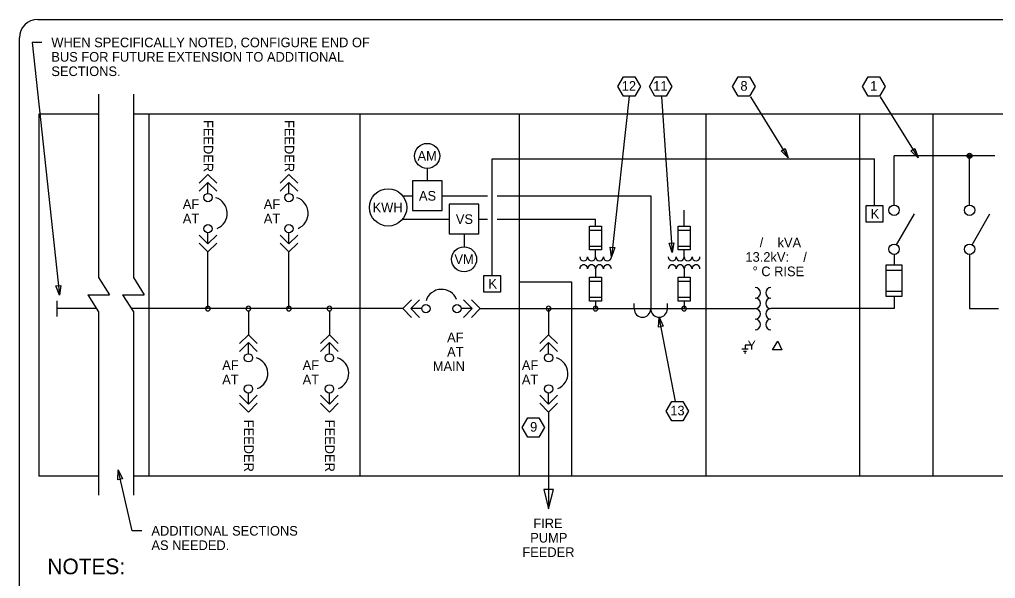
# Model space of a CAD drawing. Extents: x 10270 to 10376, y 10097 to 10174.
# Drawn here: x 10270.4 to 10338.1, y 10135.3 to 10174.1 of the extents above; entities that cross this region are included whole.
import ezdxf

# ---------------------------------------------------------------- set-up
doc = ezdxf.new("R2010")
doc.units = 0
for name, color, linetype in [('G-ANNO-TEXT', 7, 'Continuous'), ('G-ANNO-TTLB', 7, 'Continuous'), ('G-DETL-LINE', 7, 'Continuous'), ('G-DETL-OTLN', 7, 'Continuous'), ('G-DETL-PATT', 7, 'Continuous')]:
    doc.layers.add(name, color=color, linetype=linetype)

msp = doc.modelspace()

# ---------------------------------------------------------------- linework, layer by layer
at = {"layer": 'G-ANNO-TEXT'}
for p, q in [((10271.92, 10172.538), (10271.253, 10172.538)), ((10271.253, 10172.538), (10273.142, 10154.997)), ((10275.86, 10168.936), (10275.86, 10156.215)), ((10278.273, 10168.936), (10278.273, 10156.215)), ((10312.673, 10168.798), (10311.437, 10157.653)), ((10314.903, 10168.781), (10315.653, 10157.955)), ((10321.077, 10168.761), (10323.706, 10164.527)), ((10330.08, 10168.761), (10332.709, 10164.527)), ((10275.86, 10156.215), (10276.614, 10155.022)), ((10278.273, 10156.215), (10279.027, 10155.022)), ((10275.105, 10155.022), (10275.86, 10153.829)), ((10275.105, 10155.022), (10276.614, 10155.022)), ((10277.518, 10155.022), (10278.273, 10153.829)), ((10277.518, 10155.022), (10279.027, 10155.022)), ((10275.86, 10153.829), (10275.86, 10141.108)), ((10278.273, 10153.829), (10278.273, 10141.108)), ((10315.892, 10147.627), (10314.744, 10153.465)), ((10320.935, 10151.25), (10320.484, 10151.25)), ((10321.218, 10151.515), (10320.709, 10151.516)), ((10320.709, 10151.515), (10320.709, 10151.25)), ((10322.623, 10151.212), (10322.977, 10151.815)), ((10322.977, 10151.815), (10323.26, 10151.212)), ((10320.819, 10151.097), (10320.612, 10151.097)), ((10320.767, 10150.973), (10320.664, 10150.973)), ((10323.26, 10151.212), (10322.623, 10151.212)), ((10278.194, 10138.643), (10277.214, 10142.865)), ((10278.861, 10138.643), (10278.194, 10138.643))]:
    msp.add_line(p, q, dxfattribs=at)
for points in [[(10313.457, 10169.477), (10313.065, 10168.798), (10312.28, 10168.798), (10311.888, 10169.477), (10312.28, 10170.156), (10313.065, 10170.156)], [(10315.639, 10169.477), (10315.247, 10168.798), (10314.463, 10168.798), (10314.071, 10169.477), (10314.463, 10170.156), (10315.247, 10170.156)], [(10321.417, 10169.477), (10321.025, 10168.798), (10320.24, 10168.798), (10319.848, 10169.477), (10320.24, 10170.156), (10321.025, 10170.156)], [(10330.42, 10169.477), (10330.028, 10168.798), (10329.243, 10168.798), (10328.851, 10169.477), (10329.243, 10170.156), (10330.028, 10170.156)], [(10323.496, 10165.182), (10323.706, 10164.527), (10323.213, 10165.006)], [(10332.499, 10165.182), (10332.709, 10164.527), (10332.216, 10165.006)], [(10311.676, 10158.297), (10311.437, 10157.653), (10311.345, 10158.334)], [(10315.773, 10158.631), (10315.653, 10157.955), (10315.44, 10158.608)], [(10273.236, 10155.678), (10273.142, 10154.997), (10272.904, 10155.642)], [(10314.709, 10152.779), (10314.744, 10153.465), (10315.036, 10152.844)], [(10316.796, 10146.944), (10316.404, 10146.265), (10315.62, 10146.265), (10315.228, 10146.944), (10315.62, 10147.623), (10316.404, 10147.623)], [(10306.807, 10145.811), (10306.415, 10145.131), (10305.631, 10145.131), (10305.239, 10145.811), (10305.631, 10146.49), (10306.415, 10146.49)], [(10277.202, 10142.178), (10277.214, 10142.865), (10277.527, 10142.254)]]:
    msp.add_lwpolyline(points, close=True, dxfattribs=at)
at = {"layer": 'G-ANNO-TTLB'}
msp.add_line((10270.377, 10111.037), (10270.377, 10172.868), dxfattribs=at)
msp.add_lwpolyline([(10271.638, 10174.128), (10374.658, 10174.128)], dxfattribs=at)
msp.add_arc((10271.638, 10172.868), 1.261, 90, 180, dxfattribs=at)
at = {"layer": 'G-DETL-LINE'}
for p, q in [((10331.046, 10161.967), (10331.046, 10164.67)), ((10336.287, 10161.967), (10336.287, 10164.67)), ((10283.451, 10163.375), (10282.841, 10162.765)), ((10283.451, 10162.821), (10282.841, 10162.21)), ((10283.451, 10163.375), (10284.061, 10162.765)), ((10283.451, 10162.821), (10284.061, 10162.21)), ((10283.451, 10162.057), (10283.451, 10162.821)), ((10289.068, 10163.375), (10288.458, 10162.765)), ((10289.068, 10162.821), (10288.458, 10162.21)), ((10289.068, 10163.375), (10289.678, 10162.765)), ((10289.068, 10162.821), (10289.678, 10162.21)), ((10289.068, 10162.057), (10289.068, 10162.821)), ((10331.046, 10161.247), (10331.046, 10161.967)), ((10336.287, 10161.247), (10336.287, 10161.967)), ((10331.227, 10158.495), (10332.461, 10160.633)), ((10336.468, 10158.495), (10337.702, 10160.633)), ((10283.451, 10158.561), (10282.841, 10159.171)), ((10283.451, 10158.561), (10283.451, 10159.324)), ((10283.451, 10158.561), (10284.061, 10159.171)), ((10289.068, 10158.561), (10288.458, 10159.171)), ((10289.068, 10158.561), (10289.068, 10159.324)), ((10289.068, 10158.561), (10289.678, 10159.171)), ((10283.451, 10158.006), (10282.841, 10158.616)), ((10283.451, 10158.006), (10284.061, 10158.616)), ((10289.068, 10158.006), (10288.458, 10158.616)), ((10289.068, 10158.006), (10289.678, 10158.616)), ((10283.451, 10154.061), (10283.451, 10158.006)), ((10289.068, 10154.061), (10289.068, 10158.006)), ((10331.046, 10157.822), (10331.046, 10157.101)), ((10336.287, 10157.822), (10336.287, 10157.101)), ((10330.497, 10157.101), (10331.595, 10157.101)), ((10330.497, 10154.904), (10330.497, 10157.101)), ((10330.497, 10156.735), (10331.595, 10156.735)), ((10331.595, 10157.101), (10331.595, 10154.904)), ((10336.287, 10157.101), (10336.287, 10154.061)), ((10296.963, 10154.061), (10297.573, 10154.671)), ((10297.517, 10154.061), (10298.128, 10154.671)), ((10301.777, 10154.061), (10301.167, 10154.671)), ((10302.332, 10154.061), (10301.722, 10154.671)), ((10330.497, 10155.27), (10331.595, 10155.27)), ((10331.595, 10154.904), (10330.497, 10154.904)), ((10331.046, 10154.904), (10331.046, 10154.061)), ((10272.965, 10154.608), (10272.965, 10153.514)), ((10275.692, 10154.061), (10272.965, 10154.061)), ((10296.963, 10154.061), (10278.094, 10154.061)), ((10296.963, 10154.061), (10297.573, 10153.451)), ((10297.517, 10154.061), (10298.128, 10153.451)), ((10298.281, 10154.061), (10297.517, 10154.061)), ((10301.777, 10154.061), (10301.014, 10154.061)), ((10301.777, 10154.061), (10301.167, 10153.451)), ((10302.332, 10154.061), (10301.722, 10153.451)), ((10302.332, 10154.061), (10321.411, 10154.061)), ((10307.085, 10154.068), (10307.085, 10152.254)), ((10331.046, 10154.061), (10322.51, 10154.061)), ((10336.287, 10154.061), (10338.296, 10154.061)), ((10286.259, 10153.898), (10286.259, 10152.254)), ((10291.877, 10153.898), (10291.877, 10152.254)), ((10286.259, 10152.254), (10285.649, 10151.644)), ((10286.259, 10152.254), (10286.869, 10151.644)), ((10291.877, 10152.254), (10291.267, 10151.644)), ((10291.877, 10152.254), (10292.487, 10151.644)), ((10307.085, 10152.254), (10306.475, 10151.644)), ((10307.085, 10152.254), (10307.695, 10151.644)), ((10286.259, 10151.7), (10285.649, 10151.089)), ((10286.259, 10151.7), (10286.869, 10151.089)), ((10286.259, 10150.936), (10286.259, 10151.7)), ((10291.877, 10151.7), (10291.267, 10151.089)), ((10291.877, 10151.7), (10292.487, 10151.089)), ((10291.877, 10150.936), (10291.877, 10151.7)), ((10307.085, 10151.7), (10306.475, 10151.089)), ((10307.085, 10151.7), (10307.695, 10151.089)), ((10307.085, 10150.936), (10307.085, 10151.7)), ((10286.259, 10147.44), (10285.649, 10148.05)), ((10286.259, 10147.44), (10286.259, 10148.203)), ((10286.259, 10147.44), (10286.869, 10148.05)), ((10291.877, 10147.44), (10291.267, 10148.05)), ((10291.877, 10147.44), (10291.877, 10148.203)), ((10291.877, 10147.44), (10292.487, 10148.05)), ((10307.085, 10147.44), (10306.475, 10148.05)), ((10307.085, 10147.44), (10307.085, 10148.203)), ((10307.085, 10147.44), (10307.695, 10148.05)), ((10286.259, 10146.885), (10285.649, 10147.495)), ((10286.259, 10146.885), (10286.869, 10147.495)), ((10291.877, 10146.885), (10291.267, 10147.495)), ((10291.877, 10146.885), (10292.487, 10147.495)), ((10307.085, 10146.885), (10306.475, 10147.495)), ((10307.085, 10146.885), (10307.695, 10147.495)), ((10307.085, 10146.885), (10307.085, 10140.17))]:
    msp.add_line(p, q, dxfattribs=at)
msp.add_lwpolyline([(10338.046, 10164.67), (10331.046, 10164.67)], dxfattribs=at)
msp.add_lwpolyline([(10306.751, 10141.503), (10307.085, 10140.17), (10307.418, 10141.503)], close=True, dxfattribs=at)
for centre, radius in [((10336.287, 10164.67), 0.174), ((10336.287, 10164.67), 0.0977), ((10336.287, 10164.67), 0.0326), ((10283.451, 10161.769), 0.287), ((10289.068, 10161.769), 0.287), ((10331.046, 10160.886), 0.36), ((10336.287, 10160.886), 0.36), ((10283.451, 10159.611), 0.287), ((10289.068, 10159.611), 0.287), ((10331.046, 10158.182), 0.36), ((10336.287, 10158.182), 0.36), ((10298.569, 10154.061), 0.287), ((10300.727, 10154.061), 0.287), ((10286.259, 10150.648), 0.287), ((10291.877, 10150.648), 0.287), ((10307.085, 10150.648), 0.287), ((10286.259, 10148.49), 0.287), ((10291.877, 10148.49), 0.287), ((10307.085, 10148.49), 0.287)]:
    msp.add_circle(centre, radius, dxfattribs=at)
for centre, radius, start, end in [((10283.661, 10160.683), 1.13, 291.91165, 72.57617), ((10289.278, 10160.683), 1.13, 291.91165, 72.57617), ((10299.655, 10154.271), 1.13, 21.91165, 162.57617), ((10321.411, 10155.16), 0.366, 270.00003, 90.00003), ((10322.51, 10155.16), 0.366, 90.00003, 270.00003), ((10321.411, 10154.427), 0.366, 270.00003, 90.00003), ((10322.51, 10154.427), 0.366, 90.00003, 270.00003), ((10283.45, 10154.061), 0.163, 360, 180), ((10283.45, 10154.061), 0.163, 180, 0), ((10286.259, 10154.061), 0.163, 360, 180), ((10286.259, 10154.061), 0.163, 180, 0), ((10289.068, 10154.061), 0.163, 360, 180), ((10289.068, 10154.061), 0.163, 360, 180), ((10289.068, 10154.061), 0.163, 180, 0), ((10289.068, 10154.061), 0.163, 180, 0), ((10291.877, 10154.061), 0.163, 360, 180), ((10291.877, 10154.061), 0.163, 180, 0), ((10307.078, 10154.061), 0.163, 360, 180), ((10307.078, 10154.061), 0.163, 180, 0), ((10321.411, 10153.695), 0.366, 270.00003, 90.00003), ((10322.51, 10153.695), 0.366, 90.00003, 270.00003), ((10321.411, 10152.962), 0.366, 270.00003, 90.00003), ((10322.51, 10152.962), 0.366, 90.00003, 270.00003), ((10286.47, 10149.562), 1.13, 291.91165, 72.57617), ((10292.087, 10149.562), 1.13, 291.91165, 72.57617), ((10307.295, 10149.562), 1.13, 291.91165, 72.57617)]:
    msp.add_arc(centre, radius, start, end, dxfattribs=at)
at = {"layer": 'G-DETL-OTLN'}
for p, q in [((10275.86, 10167.562), (10271.724, 10167.562)), ((10271.724, 10167.562), (10271.724, 10142.435)), ((10344.565, 10167.562), (10278.273, 10167.562)), ((10279.349, 10167.562), (10279.349, 10142.435)), ((10293.975, 10167.562), (10293.975, 10142.435)), ((10305.045, 10167.562), (10305.045, 10142.435)), ((10317.991, 10167.562), (10317.991, 10142.435)), ((10328.655, 10167.562), (10328.655, 10142.435)), ((10333.749, 10167.562), (10333.749, 10142.435)), ((10275.86, 10142.435), (10271.724, 10142.435)), ((10344.565, 10142.435), (10278.273, 10142.435))]:
    msp.add_line(p, q, dxfattribs=at)
msp.add_lwpolyline([(10305.071, 10155.917), (10308.676, 10155.917), (10308.676, 10142.435)], dxfattribs=at)
at = {"layer": 'G-DETL-PATT'}
for p, q in [((10329.693, 10161.227), (10329.693, 10164.455)), ((10298.659, 10163.793), (10298.659, 10162.921)), ((10296.957, 10161.894), (10297.632, 10161.894)), ((10299.687, 10161.894), (10302.844, 10161.894)), ((10303.511, 10161.894), (10314.168, 10161.894)), ((10314.168, 10161.894), (10314.168, 10154.061)), ((10316.485, 10159.782), (10316.485, 10160.89)), ((10296.957, 10160.275), (10300.191, 10160.275)), ((10302.246, 10160.275), (10302.844, 10160.275)), ((10303.511, 10160.275), (10310.338, 10160.275)), ((10310.338, 10159.782), (10310.338, 10160.275)), ((10309.926, 10159.782), (10310.75, 10159.782)), ((10309.926, 10158.134), (10309.926, 10159.782)), ((10309.926, 10159.507), (10310.75, 10159.507)), ((10310.75, 10159.782), (10310.75, 10158.134)), ((10316.073, 10159.782), (10316.897, 10159.782)), ((10316.073, 10158.134), (10316.073, 10159.782)), ((10316.073, 10159.507), (10316.897, 10159.507)), ((10316.897, 10159.782), (10316.897, 10158.134)), ((10301.219, 10159.247), (10301.219, 10158.356)), ((10309.926, 10158.408), (10310.75, 10158.408)), ((10310.75, 10158.134), (10309.926, 10158.134)), ((10310.338, 10157.653), (10310.338, 10158.134)), ((10316.073, 10158.408), (10316.897, 10158.408)), ((10316.897, 10158.134), (10316.073, 10158.134)), ((10316.485, 10157.653), (10316.485, 10158.134)), ((10310.338, 10156.829), (10310.338, 10156.239)), ((10316.485, 10156.829), (10316.485, 10156.239)), ((10309.926, 10156.239), (10310.75, 10156.239)), ((10309.926, 10154.591), (10309.926, 10156.239)), ((10310.75, 10156.239), (10310.75, 10154.591)), ((10316.073, 10156.239), (10316.897, 10156.239)), ((10316.073, 10154.591), (10316.073, 10156.239)), ((10316.897, 10156.239), (10316.897, 10154.591)), ((10309.926, 10155.965), (10310.75, 10155.965)), ((10316.073, 10155.965), (10316.897, 10155.965)), ((10309.926, 10154.866), (10310.75, 10154.866)), ((10316.073, 10154.866), (10316.897, 10154.866)), ((10310.75, 10154.591), (10309.926, 10154.591)), ((10310.338, 10154.591), (10310.338, 10154.061)), ((10313.017, 10154.04), (10313.017, 10154.412)), ((10315.319, 10154.04), (10315.319, 10154.412)), ((10316.897, 10154.591), (10316.073, 10154.591)), ((10316.485, 10154.591), (10316.485, 10154.061))]:
    msp.add_line(p, q, dxfattribs=at)
msp.add_lwpolyline([(10303.177, 10156.37), (10303.177, 10164.455), (10329.694, 10164.455)], dxfattribs=at)
for points in [[(10299.687, 10162.921), (10297.632, 10162.921), (10297.632, 10160.866), (10299.687, 10160.866)], [(10302.246, 10161.302), (10300.191, 10161.302), (10300.191, 10159.247), (10302.246, 10159.247)], [(10329.114, 10160.07), (10329.114, 10161.227), (10330.272, 10161.227), (10330.272, 10160.07)], [(10302.598, 10155.212), (10302.598, 10156.37), (10303.756, 10156.37), (10303.756, 10155.212)]]:
    msp.add_lwpolyline(points, close=True, dxfattribs=at)
for centre, radius in [((10298.659, 10164.663), 0.87), ((10295.947, 10161.084), 1.294), ((10301.219, 10157.486), 0.87)]:
    msp.add_circle(centre, radius, dxfattribs=at)
for centre, radius, start, end in [((10309.514, 10157.653), 0.275, 180.00003, 0.00003), ((10310.063, 10157.653), 0.275, 180.00003, 0.00003), ((10310.613, 10157.653), 0.275, 180.00003, 0.00003), ((10311.163, 10157.653), 0.275, 180.00003, 0.00003), ((10315.661, 10157.653), 0.275, 180.00003, 0.00003), ((10316.21, 10157.653), 0.275, 180.00003, 0.00003), ((10316.76, 10157.653), 0.275, 180.00003, 0.00003), ((10317.309, 10157.653), 0.275, 180.00003, 0.00003), ((10309.514, 10156.829), 0.275, 0.00003, 180.00003), ((10310.063, 10156.829), 0.275, 0.00003, 180.00003), ((10310.613, 10156.829), 0.275, 0.00003, 180.00003), ((10311.163, 10156.829), 0.275, 0.00003, 180.00003), ((10315.661, 10156.829), 0.275, 0.00003, 180.00003), ((10316.21, 10156.829), 0.275, 0.00003, 180.00003), ((10316.76, 10156.829), 0.275, 0.00003, 180.00003), ((10317.309, 10156.829), 0.275, 0.00003, 180.00003), ((10310.338, 10154.061), 0.163, 360, 180), ((10310.338, 10154.061), 0.163, 180, 0), ((10313.593, 10154.041), 0.575, 180, 0), ((10314.744, 10154.041), 0.575, 180, 0), ((10316.485, 10154.061), 0.163, 360, 180), ((10316.485, 10154.061), 0.163, 180, 0)]:
    msp.add_arc(centre, radius, start, end, dxfattribs=at)

# ---------------------------------------------------------------- texts
at = {"layer": 'G-ANNO-TEXT'}
for s, height, p in [('WHEN SPECIFICALLY NOTED, CONFIGURE END OF', 0.66667, (10272.586, 10172.204)), ('BUS FOR FUTURE EXTENSION TO ADDITIONAL', 0.66667, (10272.586, 10171.204)), ('SECTIONS.', 0.6667, (10272.586, 10170.204)), ('12', 0.6667, (10312.158, 10169.187)), ('11', 0.6667, (10314.341, 10169.187)), ('8', 0.667, (10320.388, 10169.187)), ('1', 0.667, (10329.391, 10169.187)), ('AM', 0.6667, (10297.989, 10164.33)), ('AS', 0.6667, (10298.088, 10161.56)), ('   AF', 0.6667, (10280.962, 10160.981)), ('   AF', 0.6667, (10286.58, 10160.981)), ('KWH', 0.6667, (10294.871, 10160.751)), ('   AT', 0.6667, (10280.962, 10159.981)), ('   AT', 0.6667, (10286.58, 10159.981)), ('VS', 0.6667, (10300.648, 10159.942)), ('    /    kVA', 0.66667, (10320.738, 10158.315)), ('13.2kV:    /    ', 0.66667, (10320.738, 10157.315)), ('VM', 0.6667, (10300.55, 10157.153)), ('  ° C RISE', 0.6667, (10320.738, 10156.315)), ('    AF', 0.6667, (10299.049, 10151.733)), ('    AT', 0.6667, (10299.049, 10150.733)), ('   AF', 0.6667, (10283.698, 10149.808)), ('   AF', 0.6667, (10289.277, 10149.808)), ('MAIN', 0.6667, (10299.049, 10149.733)), ('   AF', 0.6667, (10304.485, 10149.808)), ('   AT', 0.6667, (10283.698, 10148.808)), ('   AT', 0.6667, (10289.277, 10148.808)), ('   AT', 0.6667, (10304.485, 10148.808)), ('13', 0.6667, (10315.524, 10146.654)), ('9', 0.667, (10305.798, 10145.52)), ('FIRE', 0.6667, (10306.023, 10138.826)), ('ADDITIONAL SECTIONS', 0.66667, (10279.528, 10138.309)), ('PUMP', 0.6667, (10305.808, 10137.826)), ('AS NEEDED.', 0.6667, (10279.528, 10137.309)), ('FEEDER', 0.6667, (10305.263, 10136.826)), ('NOTES:', 1.0833, (10272.312, 10135.628))]:
    msp.add_text(s, height=height, dxfattribs=at).set_placement(p)
for s, height, rotation, p in [('FEEDER', 0.6667, 270, (10283.147, 10167.152)), ('FEEDER', 0.6667, 270, (10288.765, 10167.152)), ('Y', 0.617, 360, (10320.894, 10151.213)), ('FEEDER', 0.6667, 270, (10285.955, 10146.348)), ('FEEDER', 0.6667, 270, (10291.573, 10146.348))]:
    msp.add_text(s, height=height, rotation=rotation, dxfattribs=at).set_placement(p)
at = {"layer": 'G-DETL-PATT'}
for p in [(10329.424, 10160.315), (10302.908, 10155.458)]:
    msp.add_text('K', height=0.667, rotation=360, dxfattribs=at).set_placement(p)

doc.saveas('drawing.dxf')
